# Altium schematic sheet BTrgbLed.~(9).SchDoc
size A4
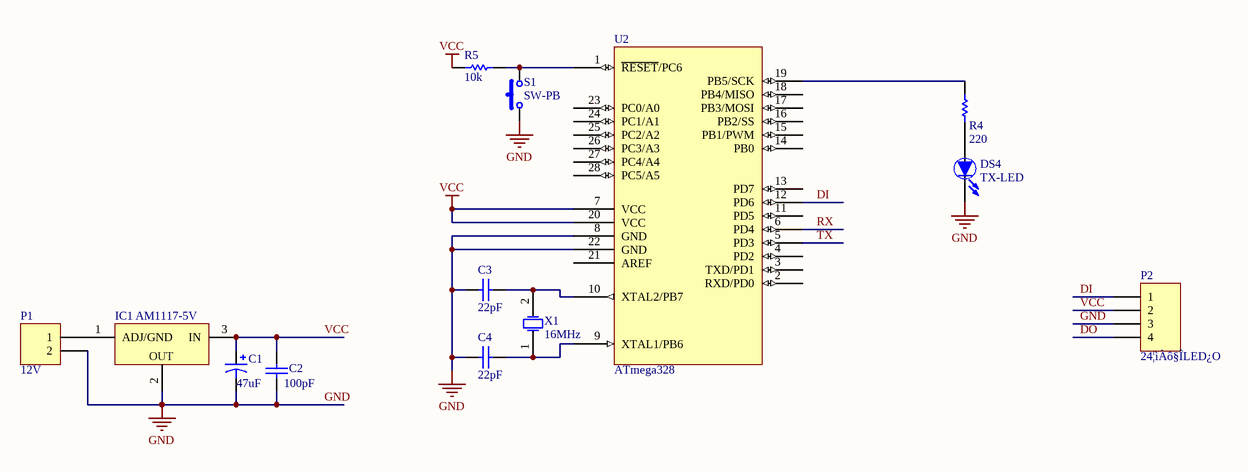
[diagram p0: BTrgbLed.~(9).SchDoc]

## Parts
C1  47uF  [RB7.6-15]
C2  value 100pF  [RAD-0.3]  (hidden comment: Cap)
C3  22pF  [C200]
C4  22pF  [C200]
DS4  TX-LED  [LED-3mm_G]
IC1  AM1117-5V  [SOT-223]
P1  12V  [HDR1X2]
P2  24¦ìÀô§ÎLED¿O  [HDR1X4]
R4  220  [AXIAL-0.3]
R5  10k  [AXIAL-0.3]
S1  SW-PB  [TACK6]
U2  ATmega328  [DIP28]
X1  16MHz  [XTAL4-8]

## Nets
GND: C1.2 C2.2 C3.1 C4.1 DS4.2(K) IC1.2(OUT) P1.2 P2.3 S1.1 U2.8(GND) U2.22(GND)
VCC: C1.1 C2.1 IC1.3(IN) P2.2 R5.1 U2.7(VCC) U2.20(VCC)
DI: P2.1 U2.12(PD6)
DO: P2.4
RX: U2.6(PD4)
TX: U2.5(PD3)
NetC3_2: C3.2 U2.10(XTAL2/PB7) X1.2(OSC2)
NetC4_2: C4.2 U2.9(XTAL1/PB6) X1.1(OSC1)
NetDS4_1: DS4.1(A) R4.1
NetIC1_1: IC1.1(ADJ/GND) P1.1
NetR4_2: R4.2 U2.19(PB5/SCK)
NetR5_2: R5.2 S1.2 U2.1(~{RESET}/PC6)

Not connected (* = marked no-connect by the designer): U2 2(RXD/PD0) 3(TXD/PD1) 4(PD2) 11(PD5) 13(PD7) 14(PB0) 15(PB1/PWM) 16(PB2/SS) 17(PB3/MOSI) 18(PB4/MISO) 21(AREF) 23(PC0/A0) 24(PC1/A1) 25(PC2/A2) 26(PC3/A3) 27(PC4/A4) 28(PC5/A5)

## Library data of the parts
C1 = Cap Pol1: Polarized Capacitor (Radial)
C2-C4 = Cap: Capacitor
DS4 = LED: Typical INFRARED GaAs LED
IC1 = AM1117
P1 = Header 2: Header, 2-Pin
P2 = Header 4: Header, 4-Pin
R4 R5 = Res: Resistor
S1 = SW-PB: Switch
U2 = ATmega328: ATmega¨t¦C³æ´¹¤ù
X1 = XTAL: Crystal Oscillator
